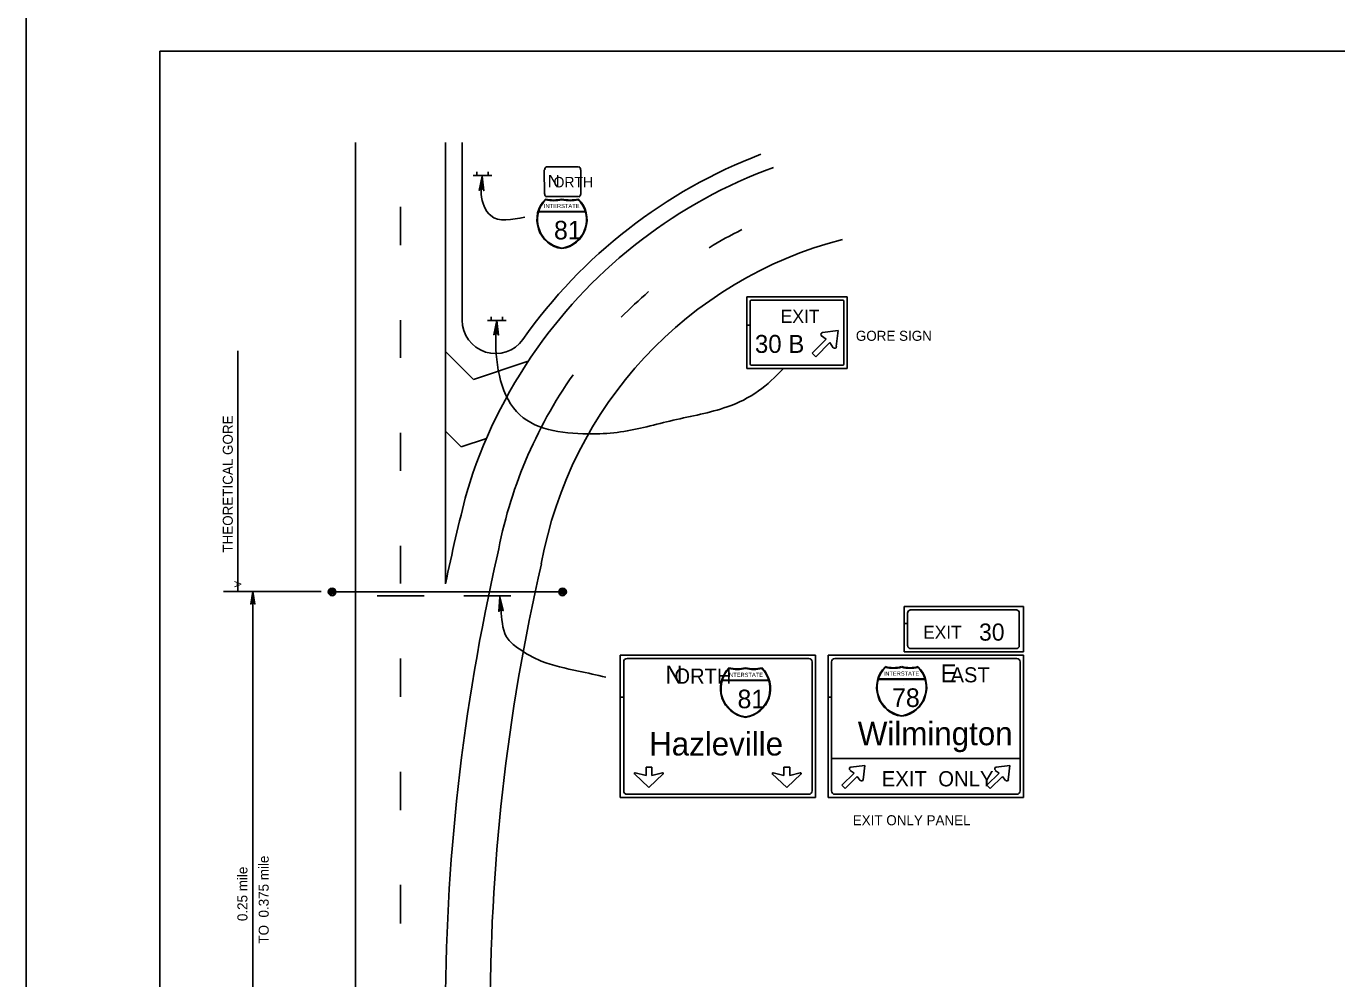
# Model space of a CAD drawing. Extents: x 644898 to 648326, y 298294 to 300670.
# Drawn here: x 644898.3 to 645290.3, y 299190.1 to 299475 of the extents above; entities that cross this region are included whole.
import ezdxf

# ---------------------------------------------------------------- set-up
doc = ezdxf.new("R2010")
doc.units = 0
for name, color, linetype in [('1', 7, 'Continuous'), ('2', 7, 'Continuous'), ('XCS-GRID-MIN', 7, 'Continuous')]:
    doc.layers.add(name, color=color, linetype=linetype)

msp = doc.modelspace()

# ---------------------------------------------------------------- linework, layer by layer
at = {"layer": '1'}
for q in [(645724.32, 299467.49), (644938.32, 298903.49)]:
    msp.add_line((644938.32, 299467.49), q, dxfattribs=at)
at = {"layer": '2'}
for p, q in [((644996.85, 299162.17), (644996.85, 299440.25)), ((645023.72, 299387.1), (645023.72, 299440.25)), ((645028.72, 299387.1), (645028.72, 299440.25)), ((645033.11, 299430.31), (645033.11, 299431.44)), ((645036.48, 299430.31), (645036.48, 299431.44)), ((645053.31, 299424.79), (645053.29, 299432.04)), ((645053.92, 299432.91), (645063.54, 299432.93)), ((645064.17, 299432.06), (645064.18, 299424.81)), ((645037.61, 299430.31), (645031.98, 299430.31)), ((645058.93, 299428.42), (645058.93, 299428.42)), ((645063.56, 299424.06), (645053.94, 299424.04)), ((645010.31, 299409.56), (645010.31, 299420.94)), ((645065.57, 299419.6), (645051.69, 299419.6)), ((645053.69, 299423.1), (645053.69, 299423.1)), ((645058.57, 299423.1), (645058.57, 299423.1)), ((645063.44, 299423.1), (645063.44, 299423.1)), ((645051.57, 299419.48), (645065.57, 299419.48)), ((645058.57, 299415.85), (645058.57, 299415.85)), ((645143.86, 299394.04), (645113.86, 299394.04)), ((645113.86, 299394.04), (645113.86, 299385.62)), ((645114.86, 299385.62), (645114.86, 299392.79)), ((645115.11, 299393.04), (645142.61, 299393.04)), ((645142.86, 299392.79), (645142.86, 299373.91)), ((645143.86, 299372.66), (645143.86, 299394.04)), ((645010.31, 299375.81), (645010.31, 299387.06)), ((645023.72, 299308.28), (645023.72, 299387.1)), ((645041.87, 299386.99), (645036.25, 299386.99)), ((645037.37, 299386.99), (645037.37, 299388.11)), ((645040.75, 299386.99), (645040.75, 299388.11)), ((645114.86, 299385.62), (645113.86, 299385.62)), ((645113.86, 299385.62), (645113.86, 299372.66)), ((645113.86, 299385.62), (645114.86, 299385.62)), ((645114.86, 299373.91), (645114.86, 299385.62)), ((645133.46, 299377.23), (645137.59, 299381.36)), ((645138.71, 299380.36), (645134.46, 299376.11)), ((645137.59, 299381.36), (645136.21, 299382.36)), ((645136.46, 299383.36), (645141.21, 299383.98)), ((645139.71, 299378.86), (645138.71, 299380.36)), ((645141.21, 299383.98), (645140.59, 299379.23)), ((644961.62, 299377.94), (644961.62, 299305.94)), ((645023.72, 299377.73), (645032.07, 299369.38)), ((645134.46, 299376.11), (645133.46, 299377.23)), ((645032.07, 299369.38), (645048.51, 299374.83)), ((645113.86, 299372.66), (645143.86, 299372.66)), ((645142.61, 299373.66), (645115.11, 299373.66)), ((645010.31, 299342.06), (645010.31, 299353.44)), ((645023.72, 299353.91), (645028.42, 299349.22)), ((645028.42, 299349.22), (645036, 299351.74)), ((645010.31, 299308.31), (645010.31, 299319.56)), ((644986.5, 299305.94), (644957.37, 299305.94)), ((644966.12, 299305.94), (644966.12, 299136.39)), ((644989.25, 299306.57), (644989, 299305.69)), ((644989.87, 299304.94), (644989, 299306.32)), ((644989, 299306.32), (644990.75, 299305.69)), ((644989.62, 299306.82), (644989.25, 299305.07)), ((644989.25, 299305.07), (644989.25, 299306.57)), ((644989.62, 299304.94), (644989.62, 299306.82)), ((644990.75, 299305.69), (644989.62, 299306.82)), ((644989.62, 299306.82), (644990.62, 299306.32)), ((644990, 299306.57), (644989.62, 299304.94)), ((644990.12, 299305.07), (644990, 299306.57)), ((644990.5, 299306.32), (644990.12, 299305.07)), ((644990.5, 299305.19), (644990.5, 299306.32)), ((645057.83, 299305.69), (645058.95, 299306.82)), ((645059.58, 299306.32), (645057.83, 299305.69)), ((645058.95, 299306.82), (645057.95, 299306.32)), ((645058.08, 299305.19), (645058.08, 299306.32)), ((645058.08, 299306.32), (645058.45, 299305.07)), ((645058.45, 299305.07), (645058.58, 299306.57)), ((645058.58, 299306.57), (645058.95, 299304.94)), ((645058.7, 299304.94), (645059.58, 299306.32)), ((645058.95, 299304.94), (645058.95, 299306.82)), ((645058.95, 299306.82), (645059.33, 299305.07)), ((645059.33, 299305.07), (645059.33, 299306.57)), ((645059.33, 299306.57), (645059.58, 299305.69)), ((644989, 299305.69), (644989.87, 299304.94)), ((644989.75, 299305.82), (645058.83, 299305.82)), ((644989.75, 299305.82), (644989.75, 299305.82)), ((645017.31, 299304.69), (645003.3, 299304.69)), ((645043.28, 299304.69), (645029.27, 299304.69)), ((645059.58, 299305.69), (645058.7, 299304.94)), ((645058.83, 299305.82), (645058.83, 299305.82)), ((645160.97, 299296.38), (645160.97, 299301.42)), ((645160.97, 299301.42), (645196.6, 299301.42)), ((645161.97, 299299.67), (645161.97, 299296.38)), ((645194.72, 299300.42), (645162.6, 299300.42)), ((645195.35, 299289.67), (645195.35, 299299.67)), ((645196.6, 299301.42), (645196.6, 299287.92)), ((645161.97, 299296.38), (645160.97, 299296.38)), ((645160.97, 299287.92), (645160.97, 299296.38)), ((645160.97, 299296.38), (645161.97, 299296.38)), ((645161.97, 299296.38), (645161.97, 299289.67)), ((645076.03, 299274.32), (645076.03, 299286.92)), ((645076.03, 299286.92), (645134.41, 299286.92)), ((645134.41, 299286.92), (645134.41, 299244.3)), ((645138.22, 299274.32), (645138.22, 299286.92)), ((645138.22, 299286.92), (645196.6, 299286.92)), ((645196.6, 299287.92), (645160.97, 299287.92)), ((645162.6, 299288.92), (645194.72, 299288.92)), ((645196.6, 299286.92), (645196.6, 299244.3)), ((645010.31, 299274.44), (645010.31, 299285.94)), ((645132.41, 299285.92), (645078.03, 299285.92)), ((645108.59, 299282.9), (645108.59, 299282.9)), ((645113.46, 299282.9), (645113.46, 299282.9)), ((645118.34, 299282.9), (645118.34, 299282.9)), ((645133.41, 299246.3), (645133.41, 299284.92)), ((645194.6, 299285.92), (645140.22, 299285.92)), ((645155.31, 299283.28), (645155.31, 299283.28)), ((645160.19, 299283.28), (645160.19, 299283.28)), ((645165.06, 299283.28), (645165.06, 299283.28)), ((645195.6, 299246.3), (645195.6, 299284.92)), ((645096.96, 299280.65), (645096.96, 299280.65)), ((645096.96, 299280.65), (645096.96, 299280.65)), ((645096.96, 299280.65), (645096.96, 299280.65)), ((645096.96, 299280.65), (645096.96, 299280.65)), ((645096.96, 299280.65), (645096.96, 299280.65)), ((645096.96, 299280.65), (645096.96, 299280.65)), ((645106.46, 299279.28), (645120.46, 299279.28)), ((645120.46, 299279.4), (645106.59, 299279.4)), ((645167.19, 299279.78), (645153.19, 299279.78)), ((645153.19, 299279.66), (645167.19, 299279.66)), ((645178.31, 299281.03), (645178.31, 299281.03)), ((645113.46, 299275.65), (645113.46, 299275.65)), ((645160.78, 299277.8), (645160.78, 299277.8)), ((645160.78, 299277.8), (645160.78, 299277.8)), ((645160.78, 299277.8), (645160.78, 299277.8)), ((645160.78, 299277.8), (645160.78, 299277.8)), ((645160.78, 299277.8), (645160.78, 299277.8)), ((645077.03, 299274.32), (645076.03, 299274.32)), ((645076.03, 299244.3), (645076.03, 299274.32)), ((645076.03, 299274.32), (645077.03, 299274.32)), ((645139.22, 299274.32), (645138.22, 299274.32)), ((645138.22, 299244.3), (645138.22, 299274.32)), ((645138.22, 299274.32), (645139.22, 299274.32)), ((645010.31, 299240.56), (645010.31, 299252.06)), ((645080.22, 299251.37), (645084.6, 299247.37)), ((645083.72, 299250.87), (645080.47, 299251.75)), ((645085.47, 299253.37), (645083.72, 299253.37)), ((645084.6, 299247.37), (645088.85, 299251.37)), ((645088.6, 299251.75), (645085.47, 299250.87)), ((645121.46, 299251.37), (645125.84, 299247.37)), ((645124.96, 299250.87), (645121.71, 299251.75)), ((645126.71, 299253.37), (645124.96, 299253.37)), ((645125.84, 299247.37), (645130.09, 299251.37)), ((645129.84, 299251.75), (645126.71, 299250.87)), ((645145.93, 299251.65), (645142.24, 299248.02)), ((645144.74, 299252.46), (645145.93, 299251.65)), ((645149.12, 299253.9), (645144.99, 299253.4)), ((645148.62, 299249.65), (645149.12, 299253.9)), ((645189.38, 299251.65), (645185.69, 299248.02)), ((645188.19, 299252.46), (645189.38, 299251.65)), ((645192.57, 299253.9), (645188.44, 299253.4)), ((645192.07, 299249.65), (645192.57, 299253.9)), ((645142.24, 299248.02), (645143.24, 299247.02)), ((645143.24, 299247.02), (645146.87, 299250.65)), ((645146.87, 299250.65), (645147.74, 299249.46)), ((645185.69, 299248.02), (645186.69, 299247.02)), ((645186.69, 299247.02), (645190.32, 299250.65)), ((645190.32, 299250.65), (645191.19, 299249.46)), ((645134.41, 299244.3), (645076.03, 299244.3)), ((645078.03, 299245.3), (645132.41, 299245.3)), ((645196.6, 299244.3), (645138.22, 299244.3)), ((645140.22, 299245.3), (645194.6, 299245.3)), ((645010.31, 299206.69), (645010.31, 299218.19))]:
    msp.add_line(p, q, dxfattribs=at)
for points in [[(645034.06, 299426.16), (645034.31, 299426.29), (645034.69, 299430.16), (645034.06, 299426.16), (645033.81, 299425.91), (645034.69, 299430.16), (645034.81, 299426.29), (645035.06, 299426.16), (645034.69, 299430.16), (645035.19, 299425.79), (645035.06, 299426.16)], [(645038.43, 299382.99), (645038.68, 299383.11), (645039.06, 299386.99), (645038.43, 299382.99), (645038.18, 299382.74), (645039.06, 299386.99), (645039.18, 299383.11), (645039.43, 299382.99), (645039.06, 299386.99), (645039.56, 299382.61), (645039.43, 299382.99)], [(644966.62, 299302.44), (644966.37, 299302.57), (644966.12, 299305.94), (644966.62, 299302.44), (644966.75, 299302.19), (644966.12, 299305.94), (644966, 299302.57), (644965.75, 299302.44), (644966.12, 299305.94), (644965.5, 299302.19), (644965.75, 299302.44)], [(645039.91, 299300.26), (645040.03, 299300.38), (645040.03, 299304.38), (645039.91, 299300.26), (645039.66, 299300.01), (645040.03, 299304.38), (645040.53, 299300.51), (645040.78, 299300.38), (645040.03, 299304.38), (645041.03, 299300.26), (645040.78, 299300.38)], [(645077.03, 299284.92), (645077.03, 299274.32)], [(645139.22, 299284.92), (645139.22, 299274.32)], [(645077.03, 299274.32), (645077.03, 299246.3)], [(645139.22, 299274.32), (645139.22, 299246.3)], [(645139.22, 299256.05), (645195.6, 299256.05)], [(645083.72, 299253.37), (645083.72, 299250.87)], [(645085.47, 299250.87), (645085.47, 299253.37)], [(645124.96, 299253.37), (645124.96, 299250.87)], [(645126.71, 299250.87), (645126.71, 299253.37)]]:
    msp.add_lwpolyline(points, dxfattribs=at)
for centre in [(644989.81, 299305.81), (645058.77, 299305.81)]:
    msp.add_circle(centre, 1.12, dxfattribs=at)
for centre, radius, start, end in [((645173.26, 299292.34), 154.56, 110.909, 144.8419), ((645173.26, 299292.34), 149.56, 110.0996, 144.8419), ((645059.81, 299417.13), 8.74, 135, 261.8699), ((645059.81, 299417.13), 8.56, 135.6924, 163.2072), ((645056.1, 299433.05), 10.04, 255.75, 284.25), ((645056.1, 299433.05), 10.23, 256.3405, 283.989), ((645061.04, 299433.05), 10.04, 255.75, 284.25), ((645057.34, 299417.13), 8.74, 278.1301, 45), ((645061.04, 299433.05), 10.23, 256.011, 283.6595), ((645057.34, 299417.13), 8.56, 16.7928, 44.3076), ((645059.81, 299417.13), 8.56, 164.4869, 261.8699), ((645057.34, 299417.13), 8.56, 278.1301, 15.5131), ((645173.26, 299292.34), 136.19, 116.544, 121.2617), ((645173.26, 299292.34), 122.82, 104.5057, 169.7518), ((645173.26, 299292.34), 136.19, 130.6836, 135.4179), ((645115.11, 299392.79), 0.25, 90, 180), ((645142.61, 299392.79), 0.25, 0, 90), ((645038.72, 299387.1), 10, 180, 324.8419), ((645136.59, 299382.81), 0.559, 94.8591, 235.5247), ((645173.26, 299292.34), 149.56, 144.8419, 163.1927), ((645140.14, 299379.21), 0.559, 213.2476, 357.1543), ((645115.11, 299373.91), 0.25, 180, 270), ((645142.61, 299373.91), 0.25, 270, 360), ((645173.26, 299292.34), 136.19, 144.8419, 169.616), ((645638.4, 299179.35), 628.05, 165.59573, 168.15396), ((645638.4, 299179.35), 614.68, 167.07042, 180.1766), ((645638.4, 299179.35), 601.31, 167.04154, 180.23471), ((645078.03, 299284.92), 1, 90, 180), ((645114.7, 299276.93), 8.74, 135, 261.8699), ((645114.7, 299276.93), 8.56, 135.6924, 163.2072), ((645110.99, 299292.85), 10.04, 255.75, 284.25), ((645110.99, 299292.85), 10.23, 256.3405, 283.989), ((645115.94, 299292.85), 10.04, 255.75, 284.25), ((645112.23, 299276.93), 8.74, 278.1301, 45), ((645115.94, 299292.85), 10.23, 256.011, 283.6595), ((645112.23, 299276.93), 8.56, 16.7928, 44.3076), ((645132.41, 299284.92), 1, 0, 90), ((645140.22, 299284.92), 1, 90, 180), ((645161.42, 299277.28), 8.74, 135, 261.8699), ((645161.42, 299277.28), 8.56, 135.6924, 163.2072), ((645157.71, 299293.2), 10.04, 255.75, 284.25), ((645157.71, 299293.2), 10.23, 256.3405, 283.989), ((645162.66, 299293.2), 10.04, 255.75, 284.25), ((645158.95, 299277.28), 8.74, 278.1301, 45), ((645162.66, 299293.2), 10.23, 256.011, 283.6595), ((645158.95, 299277.28), 8.56, 16.7928, 44.3076), ((645194.6, 299284.92), 1, 0, 90), ((645114.7, 299276.93), 8.56, 164.4869, 261.8699), ((645112.23, 299276.93), 8.56, 278.1301, 15.5131), ((645161.42, 299277.28), 8.56, 164.4869, 261.8699), ((645158.95, 299277.28), 8.56, 278.1301, 15.5131), ((645080.45, 299251.52), 0.217, 75.9638, 226.9667), ((645088.66, 299251.52), 0.217, 313.0251, 104.0537), ((645121.69, 299251.52), 0.217, 75.9638, 226.9667), ((645129.9, 299251.52), 0.217, 313.0251, 104.0537), ((645145.04, 299252.9), 0.489, 94.8565, 235.522), ((645188.49, 299252.9), 0.489, 94.8565, 235.522), ((645148.16, 299249.75), 0.489, 213.2449, 357.1516), ((645191.61, 299249.75), 0.489, 213.2449, 357.1516), ((645078.03, 299246.3), 1, 180, 270), ((645132.41, 299246.3), 1, 270, 360), ((645140.22, 299246.3), 1, 180, 270), ((645194.6, 299246.3), 1, 270, 0)]:
    msp.add_arc(centre, radius, start, end, dxfattribs=at)
for centre, major_axis, ratio, start_param, end_param in [((645053.94, 299432.02), (0.002, -0.896), 0.6, 3.141593, 4.712389), ((645063.61, 299432.04), (-0.002, 0.896), 0.6, 4.712389, 6.283185), ((645053.95, 299424.86), (0.002, -0.896), 0.6, 4.712389, 6.283185), ((645063.63, 299424.88), (-0.002, 0.896), 0.6, 3.141593, 4.712389), ((645162.65, 299299.57), (0, -0.792), 0.827467, 3.141593, 4.712389), ((645194.68, 299299.57), (0, 0.792), 0.827467, 4.712389, 6.283185), ((645162.65, 299289.72), (0, -0.792), 0.827467, 4.712389, 6.283185), ((645194.68, 299289.72), (0, 0.792), 0.827467, 3.141593, 4.712389)]:
    msp.add_ellipse(centre, major_axis=major_axis, ratio=ratio, start_param=start_param, end_param=end_param, dxfattribs=at)
for points in [[(645034.65, 299429.57), (645034.42, 299424.75), (645037.26, 299418.35), (645047.44, 299417.86)], [(645039.02, 299386.39), (645038.79, 299381.57), (645045.96, 299358.77), (645067.75, 299353.08), (645076.11, 299353.66), (645091.86, 299357.16), (645107.98, 299361.16), (645117.36, 299365.91), (645124.61, 299372.41)], [(645040.03, 299304.38), (645040.41, 299299.51), (645042.45, 299291.7), (645045.76, 299288.79), (645052.39, 299285.14), (645063.49, 299282.16), (645071.68, 299280.32)]]:
    msp.add_spline(points, degree=3, dxfattribs=at)
at = {"layer": 'XCS-GRID-MIN'}
msp.add_lwpolyline([(644898.32, 299482.49), (645739.32, 299482.49), (645739.32, 298888.49), (644898.32, 298888.49)], close=True, dxfattribs=at)

# ---------------------------------------------------------------- texts
at = {"layer": '2'}
for s, height, rotation, p in [('N', 3.75, 0.1151, (645054.3, 299426.79)), ('ORTH', 3.125, 0.1151, (645056.05, 299426.79)), ('THEORETICAL GORE', 3, 90, (644960.12, 299317.57)), ('A', 2.09, 270, (644960.62, 299309.07)), ('TO  0.375 mile', 3, 90, (644970.86, 299200.65)), ('  0.25 mile', 3, 90, (644964.49, 299205.15))]:
    msp.add_text(s, height=height, rotation=rotation, dxfattribs=at).set_placement(p)
for s, height, p in [('INTERSTATE', 1.236, (645053.19, 299420.6)), ('81', 5.563, (645056.19, 299411.23)), ('EXIT', 3.917, (645123.98, 299386.29)), ('30 B ', 5.375, (645116.28, 299377.3)), ('GORE SIGN', 3, (645146.48, 299380.91)), ('EXIT', 3.875, (645166.61, 299291.82)), ('30', 5.125, (645183.33, 299291.25)), ('N', 5.38, (645089.46, 299278.4)), ('ORTH', 4.5, (645092.21, 299278.4)), ('E', 5.38, (645171.81, 299278.78)), ('AST', 4.5, (645174.81, 299278.78)), ('INTERSTATE', 1.236, (645108.09, 299280.4)), ('INTERSTATE', 1.236, (645154.81, 299280.78)), ('81', 5.563, (645111.09, 299271.03)), ('78', 5.563, (645157.31, 299271.41)), ('Wilmington', 7, (645147.07, 299259.97)), ('Hazleville', 7, (645084.65, 299256.9)), ('EXIT  ONLY', 4.546, (645154.22, 299247.67)), ('EXIT ONLY PANEL', 3, (645145.56, 299236.04))]:
    msp.add_text(s, height=height, dxfattribs=at).set_placement(p)

doc.saveas('drawing.dxf')
